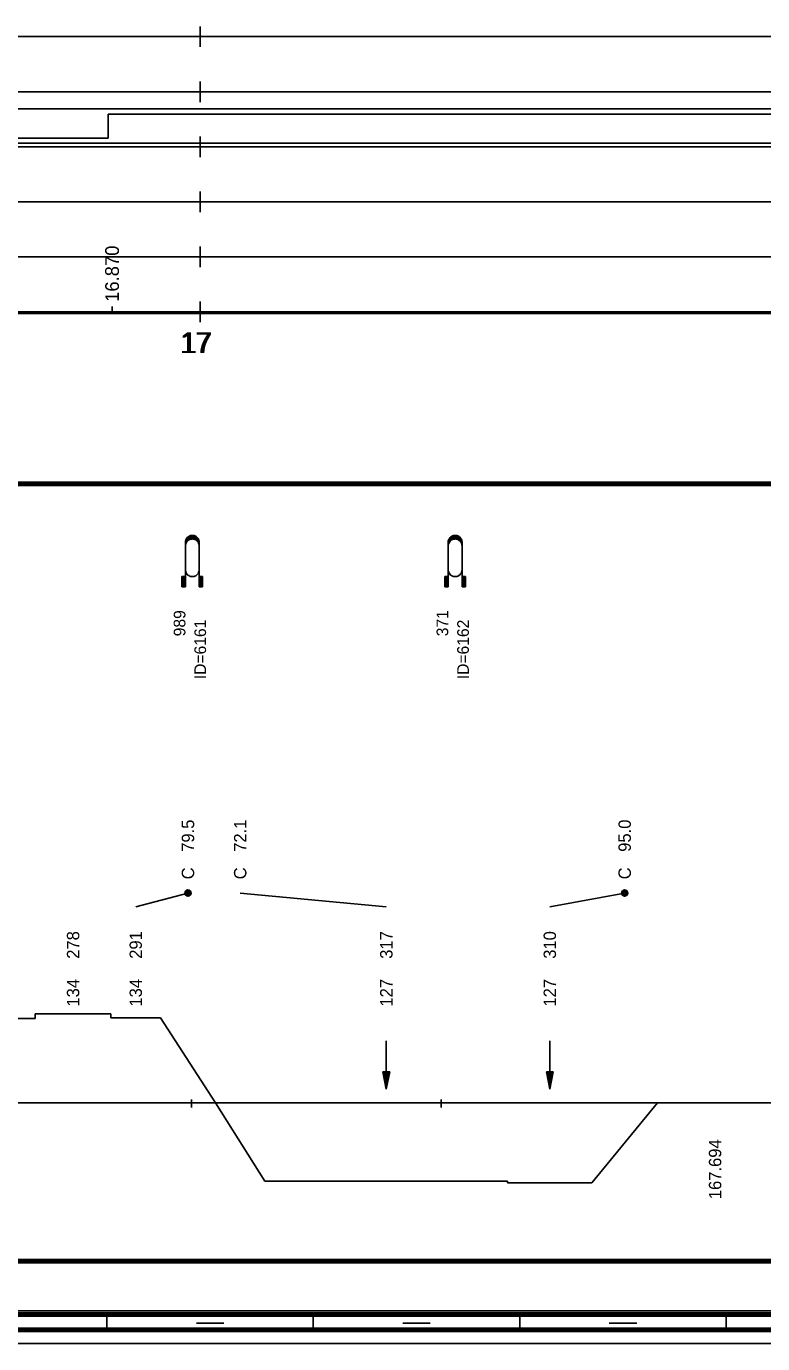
# Model space of a CAD drawing. Extents: x 2 to 10148, y 0 to 380.
# Drawn here: x 1973.3 to 2080.3, y 0 to 191.5 of the extents above; entities that cross this region are included whole.
import ezdxf

# ---------------------------------------------------------------- set-up
doc = ezdxf.new("R2010")
doc.units = 0
for name, color, linetype in [('CARA_S_OBJEKTY', 7, 'Continuous'), ('KRIV1_CARA', 7, 'Continuous'), ('KRIV1_TEXT', 7, 'Continuous'), ('OBJEKTY_TEXT', 7, 'Continuous'), ('OBJEKTY_TVAR', 7, 'Continuous'), ('RAM', 7, 'Continuous'), ('RYCHL_A', 7, 'Continuous'), ('RYCHL_B', 7, 'Continuous'), ('RYCHL_C', 7, 'Continuous'), ('RYCHL_RASTR', 7, 'Continuous'), ('RYCHL_STAN', 7, 'Continuous'), ('STAN_CARA', 7, 'Continuous'), ('STANIC_ZMEN_V', 7, 'Continuous')]:
    doc.layers.add(name, color=color, linetype=linetype)

msp = doc.modelspace()

# ---------------------------------------------------------------- linework, layer by layer
for p, q in [((1997.3, 35.51), (1997.3, 34.32)), ((2033.57, 35.51), (2033.57, 34.32))]:
    msp.add_line(p, q)
at = {"layer": 'CARA_S_OBJEKTY'}
for p, q in [((1850.83, 125.25), (2170.83, 125.25)), ((1850.83, 125), (2170.83, 125)), ((1850.83, 124.75), (2170.83, 124.75))]:
    msp.add_line(p, q, dxfattribs=at)
at = {"layer": 'KRIV1_CARA'}
for p, q in [((1974.58, 47.29), (1974.58, 47.96)), ((1974.58, 47.96), (1985.58, 47.96)), ((1985.58, 47.96), (1985.58, 47.37)), ((1963.96, 47.29), (1974.58, 47.29)), ((1985.58, 47.37), (1992.81, 47.37)), ((1992.81, 47.37), (2000.76, 35)), ((1850.83, 35), (2170.83, 35)), ((2000.76, 35), (2007.97, 23.63)), ((2055.5, 23.39), (2065, 35)), ((2007.97, 23.63), (2043.24, 23.63)), ((2043.24, 23.63), (2043.24, 23.39)), ((2043.24, 23.39), (2055.5, 23.39))]:
    msp.add_line(p, q, dxfattribs=at)
at = {"layer": 'KRIV1_TEXT'}
for p, q in [((1989.19, 63.5), (1996.78, 65.5)), ((2025.61, 63.5), (2004.37, 65.5)), ((2049.37, 63.5), (2060.25, 65.5)), ((2025.61, 44), (2025.61, 42.2)), ((2025.61, 42.2), (2025.61, 40)), ((2049.37, 44), (2049.37, 42.2)), ((2049.37, 42.2), (2049.37, 40)), ((2025.11, 39.5), (2025.61, 37)), ((2025.11, 39.5), (2026.11, 39.5)), ((2025.21, 39.5), (2025.61, 37.5)), ((2025.31, 39.5), (2025.61, 38)), ((2025.41, 39.5), (2025.61, 38.5)), ((2025.51, 39.5), (2025.61, 39)), ((2025.61, 40), (2025.61, 37)), ((2026.11, 39.5), (2025.61, 37)), ((2026.01, 39.5), (2025.61, 37.5)), ((2025.91, 39.5), (2025.61, 38)), ((2025.81, 39.5), (2025.61, 38.5)), ((2025.71, 39.5), (2025.61, 39)), ((2025.61, 39.5), (2025.61, 39.5)), ((2025.61, 39.5), (2025.61, 39.5)), ((2048.87, 39.5), (2049.37, 37)), ((2048.87, 39.5), (2049.87, 39.5)), ((2048.97, 39.5), (2049.37, 37.5)), ((2049.07, 39.5), (2049.37, 38)), ((2049.17, 39.5), (2049.37, 38.5)), ((2049.27, 39.5), (2049.37, 39)), ((2049.37, 40), (2049.37, 37)), ((2049.87, 39.5), (2049.37, 37)), ((2049.77, 39.5), (2049.37, 37.5)), ((2049.67, 39.5), (2049.37, 38)), ((2049.57, 39.5), (2049.37, 38.5)), ((2049.47, 39.5), (2049.37, 39)), ((2049.37, 39.5), (2049.37, 39.5)), ((2049.37, 39.5), (2049.37, 39.5))]:
    msp.add_line(p, q, dxfattribs=at)
for centre, radius in [((1996.78, 65.5), 0.45), ((1996.78, 65.5), 0.3), ((1996.78, 65.5), 0.15), ((2060.25, 65.5), 0.45), ((2060.25, 65.5), 0.3), ((2060.25, 65.5), 0.15)]:
    msp.add_circle(centre, radius, dxfattribs=at)
at = {"layer": 'OBJEKTY_TVAR'}
for p, q in [((1996.46, 116.81), (1996.52, 116.95)), ((1996.47, 116.85), (1996.92, 116.85)), ((1996.49, 116.9), (1997.03, 116.9)), ((1996.52, 116.95), (1996.58, 117.06)), ((1996.52, 116.95), (1997.18, 116.95)), ((1996.54, 117), (1998.28, 117)), ((1996.57, 117.05), (1998.25, 117.05)), ((1996.58, 117.06), (1996.67, 117.18)), ((1996.61, 117.1), (1998.21, 117.1)), ((1996.65, 117.15), (1998.17, 117.15)), ((1996.67, 117.18), (1996.76, 117.26)), ((1996.7, 117.2), (1998.12, 117.2)), ((1996.75, 117.25), (1998.07, 117.25)), ((1996.76, 117.26), (1996.89, 117.35)), ((1996.76, 116.74), (1996.89, 116.83)), ((1996.81, 117.3), (1998.01, 117.3)), ((1996.88, 117.35), (1997.94, 117.35)), ((1996.89, 117.35), (1997.02, 117.42)), ((1996.89, 116.83), (1997.02, 116.9)), ((1996.97, 117.4), (1997.85, 117.4)), ((1997.02, 117.42), (1997.05, 117.43)), ((1997.02, 116.9), (1997.05, 116.91)), ((1997.05, 117.43), (1997.17, 117.47)), ((1997.05, 116.91), (1997.17, 116.95)), ((1997.1, 117.45), (1997.72, 117.45)), ((1997.17, 117.47), (1997.31, 117.49)), ((1997.17, 116.95), (1997.31, 116.97)), ((1997.31, 117.49), (1997.42, 117.5)), ((1997.31, 116.97), (1997.42, 116.98)), ((1997.42, 117.5), (1997.55, 117.49)), ((1997.42, 116.98), (1997.55, 116.97)), ((1997.55, 117.49), (1997.68, 117.46)), ((1997.55, 116.97), (1997.68, 116.94)), ((1997.64, 116.95), (1998.3, 116.95)), ((1997.68, 117.46), (1997.79, 117.43)), ((1997.68, 116.94), (1997.79, 116.9)), ((1997.79, 117.43), (1997.9, 117.37)), ((1997.79, 116.9), (1997.9, 116.85)), ((1997.79, 116.9), (1998.33, 116.9)), ((1997.9, 117.37), (1997.97, 117.32)), ((1997.9, 116.85), (1998.35, 116.85)), ((1997.9, 116.85), (1997.97, 116.8)), ((1997.97, 117.32), (1998.12, 117.21)), ((1998.12, 117.21), (1998.2, 117.11)), ((1998.2, 117.11), (1998.29, 116.98)), ((1998.29, 116.98), (1998.33, 116.89)), ((1998.33, 116.89), (1998.37, 116.77)), ((2034.66, 116.81), (2034.72, 116.95)), ((2034.67, 116.85), (2035.12, 116.85)), ((2034.69, 116.9), (2035.23, 116.9)), ((2034.72, 116.95), (2034.78, 117.06)), ((2034.72, 116.95), (2035.38, 116.95)), ((2034.74, 117), (2036.48, 117)), ((2034.77, 117.05), (2036.45, 117.05)), ((2034.78, 117.06), (2034.87, 117.18)), ((2034.81, 117.1), (2036.41, 117.1)), ((2034.85, 117.15), (2036.37, 117.15)), ((2034.87, 117.18), (2034.96, 117.26)), ((2034.9, 117.2), (2036.32, 117.2)), ((2034.95, 117.25), (2036.27, 117.25)), ((2034.96, 117.26), (2035.09, 117.35)), ((2034.96, 116.74), (2035.09, 116.83)), ((2035.01, 117.3), (2036.21, 117.3)), ((2035.08, 117.35), (2036.14, 117.35)), ((2035.09, 117.35), (2035.22, 117.42)), ((2035.09, 116.83), (2035.22, 116.9)), ((2035.17, 117.4), (2036.05, 117.4)), ((2035.22, 117.42), (2035.25, 117.43)), ((2035.22, 116.9), (2035.25, 116.91)), ((2035.25, 117.43), (2035.37, 117.47)), ((2035.25, 116.91), (2035.37, 116.95)), ((2035.3, 117.45), (2035.92, 117.45)), ((2035.37, 117.47), (2035.51, 117.49)), ((2035.37, 116.95), (2035.51, 116.97)), ((2035.51, 117.49), (2035.62, 117.5)), ((2035.51, 116.97), (2035.62, 116.98)), ((2035.62, 117.5), (2035.75, 117.49)), ((2035.62, 116.98), (2035.75, 116.97)), ((2035.75, 117.49), (2035.88, 117.46)), ((2035.75, 116.97), (2035.88, 116.94)), ((2035.84, 116.95), (2036.5, 116.95)), ((2035.88, 117.46), (2035.99, 117.43)), ((2035.88, 116.94), (2035.99, 116.9)), ((2035.99, 117.43), (2036.1, 117.37)), ((2035.99, 116.9), (2036.1, 116.85)), ((2035.99, 116.9), (2036.53, 116.9)), ((2036.1, 117.37), (2036.17, 117.32)), ((2036.1, 116.85), (2036.55, 116.85)), ((2036.1, 116.85), (2036.17, 116.8)), ((2036.17, 117.32), (2036.32, 117.21)), ((2036.32, 117.21), (2036.4, 117.11)), ((2036.4, 117.11), (2036.49, 116.98)), ((2036.49, 116.98), (2036.53, 116.89)), ((2036.53, 116.89), (2036.57, 116.77)), ((1996.41, 116.5), (1996.42, 116.65)), ((1996.41, 116.55), (1996.59, 116.55)), ((1996.41, 110), (1996.41, 116.5)), ((1996.41, 116.5), (1996.56, 116.5)), ((1996.41, 116.45), (1996.53, 116.45)), ((1996.41, 116.4), (1996.5, 116.4)), ((1996.41, 116.35), (1996.48, 116.35)), ((1996.41, 116.3), (1996.46, 116.3)), ((1996.41, 116.25), (1996.45, 116.25)), ((1996.41, 116.2), (1996.44, 116.2)), ((1996.41, 116.15), (1996.43, 116.15)), ((1996.41, 115.98), (1996.42, 116.13)), ((1996.41, 116.1), (1996.42, 116.1)), ((1996.42, 116.65), (1996.46, 116.81)), ((1996.42, 116.65), (1996.67, 116.65)), ((1996.42, 116.6), (1996.63, 116.6)), ((1996.42, 116.13), (1996.46, 116.28)), ((1996.43, 116.7), (1996.72, 116.7)), ((1996.44, 116.75), (1996.78, 116.75)), ((1996.46, 116.8), (1996.84, 116.8)), ((1996.46, 116.28), (1996.52, 116.43)), ((1996.52, 116.43), (1996.58, 116.53)), ((1996.58, 116.53), (1996.67, 116.65)), ((1996.67, 116.65), (1996.76, 116.74)), ((1997.97, 116.8), (1998.12, 116.68)), ((1997.98, 116.8), (1998.36, 116.8)), ((1998.04, 116.75), (1998.38, 116.75)), ((1998.1, 116.7), (1998.39, 116.7)), ((1998.12, 116.68), (1998.2, 116.59)), ((1998.15, 116.65), (1998.4, 116.65)), ((1998.19, 116.6), (1998.4, 116.6)), ((1998.2, 116.59), (1998.29, 116.46)), ((1998.23, 116.55), (1998.41, 116.55)), ((1998.26, 116.5), (1998.41, 116.5)), ((1998.29, 116.46), (1998.33, 116.37)), ((1998.29, 116.45), (1998.41, 116.45)), ((1998.32, 116.4), (1998.41, 116.4)), ((1998.33, 116.37), (1998.37, 116.24)), ((1998.34, 116.35), (1998.41, 116.35)), ((1998.36, 116.3), (1998.41, 116.3)), ((1998.37, 116.77), (1998.4, 116.65)), ((1998.37, 116.25), (1998.41, 116.25)), ((1998.37, 116.24), (1998.4, 116.13)), ((1998.38, 116.2), (1998.41, 116.2)), ((1998.39, 116.15), (1998.41, 116.15)), ((1998.4, 116.65), (1998.41, 116.56)), ((1998.4, 116.13), (1998.41, 116.03)), ((1998.4, 116.1), (1998.41, 116.1)), ((1998.41, 116.56), (1998.41, 116.5)), ((1998.41, 116.5), (1998.41, 110)), ((1998.41, 116.03), (1998.41, 115.98)), ((2034.61, 116.5), (2034.62, 116.65)), ((2034.61, 116.55), (2034.79, 116.55)), ((2034.61, 110), (2034.61, 116.5)), ((2034.61, 116.5), (2034.76, 116.5)), ((2034.61, 116.45), (2034.73, 116.45)), ((2034.61, 116.4), (2034.7, 116.4)), ((2034.61, 116.35), (2034.68, 116.35)), ((2034.61, 116.3), (2034.66, 116.3)), ((2034.61, 116.25), (2034.65, 116.25)), ((2034.61, 116.2), (2034.64, 116.2)), ((2034.61, 116.15), (2034.63, 116.15)), ((2034.61, 115.98), (2034.62, 116.13)), ((2034.61, 116.1), (2034.62, 116.1)), ((2034.62, 116.65), (2034.66, 116.81)), ((2034.62, 116.65), (2034.87, 116.65)), ((2034.62, 116.6), (2034.83, 116.6)), ((2034.62, 116.13), (2034.66, 116.28)), ((2034.63, 116.7), (2034.92, 116.7)), ((2034.64, 116.75), (2034.98, 116.75)), ((2034.66, 116.8), (2035.04, 116.8)), ((2034.66, 116.28), (2034.72, 116.43)), ((2034.72, 116.43), (2034.78, 116.53)), ((2034.78, 116.53), (2034.87, 116.65)), ((2034.87, 116.65), (2034.96, 116.74)), ((2036.17, 116.8), (2036.32, 116.68)), ((2036.18, 116.8), (2036.56, 116.8)), ((2036.24, 116.75), (2036.58, 116.75)), ((2036.3, 116.7), (2036.59, 116.7)), ((2036.32, 116.68), (2036.4, 116.59)), ((2036.35, 116.65), (2036.6, 116.65)), ((2036.39, 116.6), (2036.6, 116.6)), ((2036.4, 116.59), (2036.49, 116.46)), ((2036.43, 116.55), (2036.61, 116.55)), ((2036.46, 116.5), (2036.61, 116.5)), ((2036.49, 116.46), (2036.53, 116.37)), ((2036.49, 116.45), (2036.61, 116.45)), ((2036.52, 116.4), (2036.61, 116.4)), ((2036.53, 116.37), (2036.57, 116.24)), ((2036.54, 116.35), (2036.61, 116.35)), ((2036.56, 116.3), (2036.61, 116.3)), ((2036.57, 116.77), (2036.6, 116.65)), ((2036.57, 116.25), (2036.61, 116.25)), ((2036.57, 116.24), (2036.6, 116.13)), ((2036.58, 116.2), (2036.61, 116.2)), ((2036.59, 116.15), (2036.61, 116.15)), ((2036.6, 116.65), (2036.61, 116.56)), ((2036.6, 116.13), (2036.61, 116.03)), ((2036.6, 116.1), (2036.61, 116.1)), ((2036.61, 116.56), (2036.61, 116.5)), ((2036.61, 116.5), (2036.61, 110)), ((2036.61, 116.03), (2036.61, 115.98)), ((1995.91, 111.5), (1996.41, 111.5)), ((1995.91, 111.5), (1995.91, 110)), ((1995.96, 111.5), (1995.96, 110)), ((1996.01, 111.5), (1996.01, 110)), ((1996.06, 111.5), (1996.06, 110)), ((1996.11, 111.5), (1996.11, 110)), ((1996.16, 111.5), (1996.16, 110)), ((1996.21, 111.5), (1996.21, 110)), ((1996.26, 111.5), (1996.26, 110)), ((1996.31, 111.5), (1996.31, 110)), ((1996.36, 111.5), (1996.36, 110)), ((1996.41, 112.5), (1996.42, 112.35)), ((1996.42, 112.35), (1996.46, 112.2)), ((1996.46, 112.2), (1996.52, 112.05)), ((1996.52, 112.05), (1996.58, 111.95)), ((1996.58, 111.95), (1996.67, 111.83)), ((1996.67, 111.83), (1996.76, 111.74)), ((1996.76, 111.74), (1996.89, 111.65)), ((1996.89, 111.65), (1997.02, 111.58)), ((1997.02, 111.58), (1997.05, 111.57)), ((1997.05, 111.57), (1997.17, 111.53)), ((1997.17, 111.53), (1997.31, 111.51)), ((1997.31, 111.51), (1997.42, 111.5)), ((1997.42, 111.5), (1997.55, 111.51)), ((1997.55, 111.51), (1997.68, 111.54)), ((1997.68, 111.54), (1997.79, 111.58)), ((1997.79, 111.58), (1997.9, 111.63)), ((1997.9, 111.63), (1997.97, 111.68)), ((1997.97, 111.68), (1998.12, 111.8)), ((1998.12, 111.8), (1998.2, 111.9)), ((1998.2, 111.9), (1998.29, 112.02)), ((1998.29, 112.02), (1998.33, 112.11)), ((1998.33, 112.11), (1998.37, 112.24)), ((1998.37, 112.24), (1998.4, 112.35)), ((1998.4, 112.35), (1998.41, 112.45)), ((1998.41, 112.45), (1998.41, 112.5)), ((1998.91, 111.5), (1998.41, 111.5)), ((1998.46, 111.5), (1998.46, 110)), ((1998.51, 111.5), (1998.51, 110)), ((1998.56, 111.5), (1998.56, 110)), ((1998.61, 111.5), (1998.61, 110)), ((1998.66, 111.5), (1998.66, 110)), ((1998.71, 111.5), (1998.71, 110)), ((1998.76, 111.5), (1998.76, 110)), ((1998.81, 111.5), (1998.81, 110)), ((1998.86, 111.5), (1998.86, 110)), ((1998.91, 111.5), (1998.91, 110)), ((2034.11, 111.5), (2034.61, 111.5)), ((2034.11, 111.5), (2034.11, 110)), ((2034.16, 111.5), (2034.16, 110)), ((2034.21, 111.5), (2034.21, 110)), ((2034.26, 111.5), (2034.26, 110)), ((2034.31, 111.5), (2034.31, 110)), ((2034.36, 111.5), (2034.36, 110)), ((2034.41, 111.5), (2034.41, 110)), ((2034.46, 111.5), (2034.46, 110)), ((2034.51, 111.5), (2034.51, 110)), ((2034.56, 111.5), (2034.56, 110)), ((2034.61, 112.5), (2034.62, 112.35)), ((2034.62, 112.35), (2034.66, 112.2)), ((2034.66, 112.2), (2034.72, 112.05)), ((2034.72, 112.05), (2034.78, 111.95)), ((2034.78, 111.95), (2034.87, 111.83)), ((2034.87, 111.83), (2034.96, 111.74)), ((2034.96, 111.74), (2035.09, 111.65)), ((2035.09, 111.65), (2035.22, 111.58)), ((2035.22, 111.58), (2035.25, 111.57)), ((2035.25, 111.57), (2035.37, 111.53)), ((2035.37, 111.53), (2035.51, 111.51)), ((2035.51, 111.51), (2035.62, 111.5)), ((2035.62, 111.5), (2035.75, 111.51)), ((2035.75, 111.51), (2035.88, 111.54)), ((2035.88, 111.54), (2035.99, 111.58)), ((2035.99, 111.58), (2036.1, 111.63)), ((2036.1, 111.63), (2036.17, 111.68)), ((2036.17, 111.68), (2036.32, 111.8)), ((2036.32, 111.8), (2036.4, 111.9)), ((2036.4, 111.9), (2036.49, 112.02)), ((2036.49, 112.02), (2036.53, 112.11)), ((2036.53, 112.11), (2036.57, 112.24)), ((2036.57, 112.24), (2036.6, 112.35)), ((2036.6, 112.35), (2036.61, 112.45)), ((2036.61, 112.45), (2036.61, 112.5)), ((2037.11, 111.5), (2036.61, 111.5)), ((2036.66, 111.5), (2036.66, 110)), ((2036.71, 111.5), (2036.71, 110)), ((2036.76, 111.5), (2036.76, 110)), ((2036.81, 111.5), (2036.81, 110)), ((2036.86, 111.5), (2036.86, 110)), ((2036.91, 111.5), (2036.91, 110)), ((2036.96, 111.5), (2036.96, 110)), ((2037.01, 111.5), (2037.01, 110)), ((2037.06, 111.5), (2037.06, 110)), ((2037.11, 111.5), (2037.11, 110)), ((1996.41, 110), (1995.91, 110)), ((1998.41, 110), (1998.91, 110)), ((2034.61, 110), (2034.11, 110)), ((2036.61, 110), (2037.11, 110))]:
    msp.add_line(p, q, dxfattribs=at)
at = {"layer": 'RAM'}
for p, q in [((1850.83, 4.75), (2170.83, 4.75)), ((1850.83, 4.5), (2170.83, 4.5)), ((1850.83, 4.25), (2170.83, 4.25)), ((1850.83, 4), (2170.83, 4)), ((1985, 2), (1985, 4)), ((2015, 2), (2015, 4)), ((2045, 2), (2045, 4)), ((2075, 2), (2075, 4)), ((1850.83, 2.25), (2170.83, 2.25)), ((1850.83, 2), (2170.83, 2)), ((1998, 3), (2002, 3)), ((2028, 3), (2032, 3)), ((2058, 3), (2062, 3)), ((1850.83, 1.75), (2170.83, 1.75)), ((1850.83, 0), (2170.83, 0))]:
    msp.add_line(p, q, dxfattribs=at)
at = {"layer": 'RYCHL_A'}
msp.add_line((1850.83, 174.5), (2170.83, 174.5), dxfattribs=at)
at = {"layer": 'RYCHL_B'}
for p, q in [((1985.17, 175.25), (1985.16, 178.75)), ((1985.16, 178.75), (2170.09, 178.75)), ((1930.37, 175.25), (1985.17, 175.25))]:
    msp.add_line(p, q, dxfattribs=at)
at = {"layer": 'RYCHL_C'}
msp.add_line((1930.38, 179.51), (2170.08, 179.5), dxfattribs=at)
at = {"layer": 'RYCHL_RASTR'}
for p, q in [((1998.55, 188.5), (1998.55, 191.5)), ((1850.83, 190), (2173.15, 190)), ((1850.83, 182), (2173.08, 182)), ((1998.55, 180.5), (1998.55, 183.5)), ((1998.55, 172.5), (1998.55, 175.5)), ((1850.83, 174), (2173.02, 174)), ((1998.55, 164.5), (1998.55, 167.5)), ((1850.83, 166), (2172.83, 166)), ((1998.55, 156.5), (1998.55, 159.5)), ((1850.83, 158), (2172.77, 158)), ((1998.55, 148.5), (1998.55, 151.5)), ((1850.83, 150), (2170.83, 150)), ((1850.83, 149.75), (2170.83, 149.75))]:
    msp.add_line(p, q, dxfattribs=at)
at = {"layer": 'STAN_CARA'}
for p, q in [((1850.83, 12.25), (2170.83, 12.25)), ((1850.83, 12), (2170.83, 12)), ((1850.83, 12), (2170.83, 12)), ((1850.83, 11.75), (2170.83, 11.75))]:
    msp.add_line(p, q, dxfattribs=at)
at = {"layer": 'STANIC_ZMEN_V'}
msp.add_line((1985.75, 150), (1985.75, 150.75), dxfattribs=at)

# ---------------------------------------------------------------- texts
at = {"layer": 'KRIV1_TEXT'}
for s, p in [('79.5', (1997.68, 71.5)), ('72.1', (2005.27, 71.5)), ('95.0', (2061.15, 71.5)), ('C', (1997.68, 67.5)), ('C', (2005.27, 67.5)), ('C', (2061.15, 67.5)), ('278', (1980.98, 55.95)), ('291', (1990.09, 55.95)), ('317', (2026.51, 55.95)), ('310', (2050.27, 55.95)), ('134', (1980.98, 49)), ('134', (1990.09, 49)), ('127', (2026.51, 49)), ('127', (2050.27, 49)), ('167.694', (2074.29, 21))]:
    msp.add_text(s, height=1.8, rotation=90, dxfattribs=at).set_placement(p)
at = {"layer": 'OBJEKTY_TEXT'}
for s, p in [('989', (1996.41, 102.83)), ('371', (2034.61, 102.83)), ('ID=6161', (1999.41, 96.59)), ('ID=6162', (2037.61, 96.59))]:
    msp.add_text(s, height=1.7, rotation=90, dxfattribs=at).set_placement(p)
at = {"layer": 'RYCHL_STAN'}
for p in [(1995.61, 144), (1995.86, 144)]:
    msp.add_text('17', height=3, dxfattribs=at).set_placement(p)
at = {"layer": 'STANIC_ZMEN_V'}
msp.add_text('16.870', height=2, rotation=90, dxfattribs=at).set_placement((1986.75, 151.45))

doc.saveas('drawing.dxf')
